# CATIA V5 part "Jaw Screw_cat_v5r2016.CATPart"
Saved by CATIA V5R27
Part number: Jaw Screw
Bounding box of the stored display mesh (mm): x -9 to 9, y 0 to 138, z -8.994 to 8.994
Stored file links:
  E:\_Deepak\2017_Deepak\CATIA\Resources\Tutorial Files\Tutorials\c13_catia_v5_6r2016_tut\c13tut2\c13tut02.CATParts\Jaw Screw_cat_v5r2016.CATPart
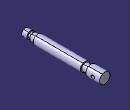
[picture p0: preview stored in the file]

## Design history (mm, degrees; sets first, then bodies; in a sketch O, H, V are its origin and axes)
Body1 (main body)
  Sketch1 on yz-plane, origin (0, 0, 0), H (0, 1, 0), V (0, 0, 1)
    line L1 (0, 0) -> (0, 6)
    line L2 (0, 6) -> (9, 6)
    line L3 (9, 6) -> (9, 4)
    line L4 (9, 4) -> (14, 4)
    line L5 (14, 4) -> (14, 6)
    point P5 (14, 6)
    line L6 (14, 6) -> (22, 6)
    line L7 (22, 6) -> (22, 8)
    line L8 (22, 8) -> (104, 8)
    line L9 (104, 8) -> (104, 6)
    point P9 (104, 6)
    line L10 (104, 6) -> (114, 6)
    line L11 (114, 6) -> (114, 9)
    line L12 (114, 9) -> (138, 9)
    line L13 (138, 9) -> (138, 0)
    point P13 (138, 0)
    line L14 (138, 0) -> (0, 0)
    distance L2 L14 = 6
    distance L8 L14 = 8
    distance L12 L14 = 9
    length L2 = 9
    length L4 = 5
    length L8 = 82
    length L10 = 10
    length L12 = 24
    length L14 = 138
    distance L4 L14 = 4
    vertical: L1 V, L3 V, L5 V, L7 V, L9 V, L11 V, L13 V
    horizontal: L2 H, L4 H, L6 H, L8 H, L10 H, L12 H, L14 H
    coincidence: P5 L2, P9 L6, P13 H
  Shaft1: profile Sketch1, axis edge of Sketch1, angle 360
  Sketch2 on yz-plane, origin (0, 0, 0), H (0, 1, 0), V (0, 0, 1)
    circle A1 centre (126, 0) radius 3
    point P1 (126, 0)
    radius A1 = 3
    distance P1 V = 126
    coincidence: P1 H
  Pocket1: profile Sketch2, direction (-1, 0, 0), length 20, mirrored extent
